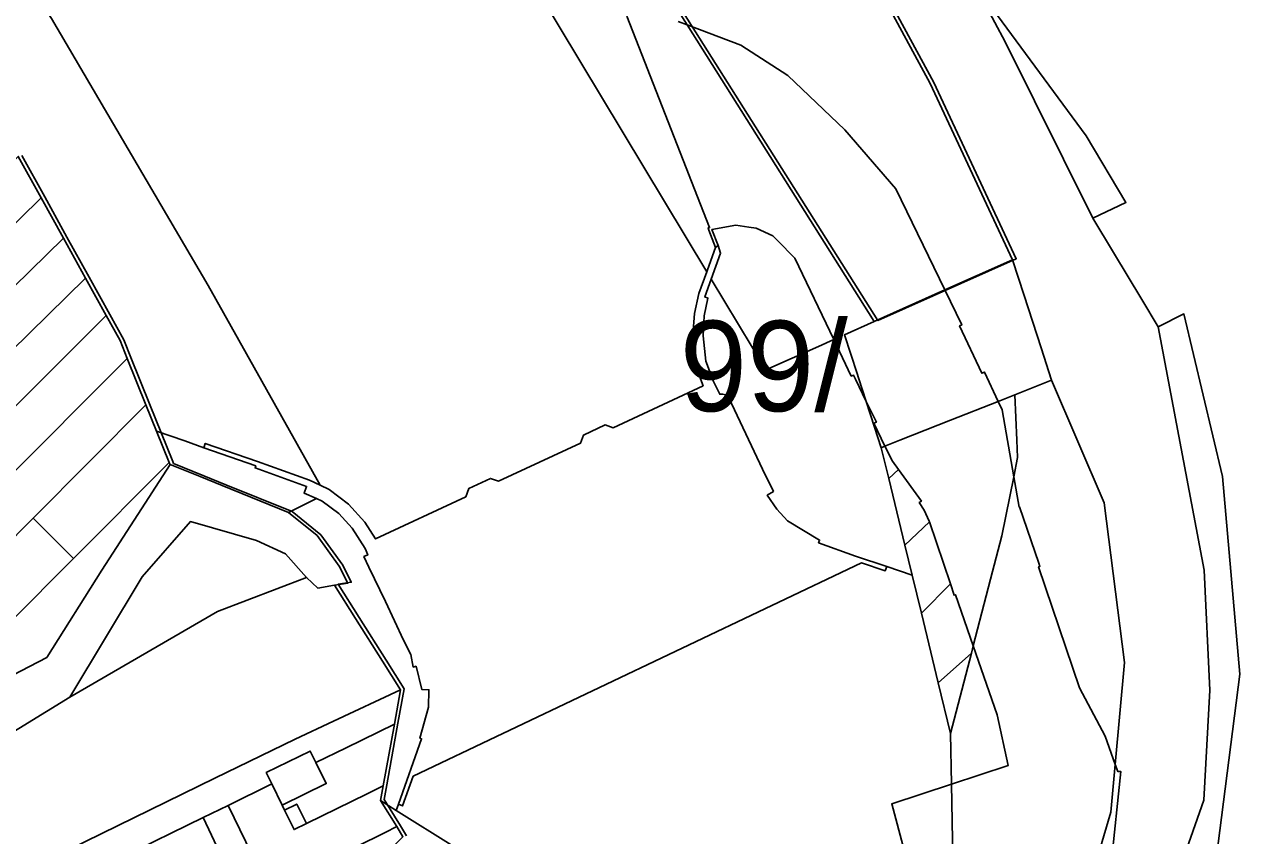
# Model space of a CAD drawing. Extents: x -535894 to -532827, y -1165802 to -1163635.
# Drawn here: x -533178.9 to -532977.3, y -1164904.6 to -1164770 of the extents above; entities that cross this region are included whole.
import ezdxf

# ---------------------------------------------------------------- set-up
doc = ezdxf.new("R2010")
doc.units = 0
for name, color, linetype in [('BPEJ_s', 7, 'Continuous'), ('orna_s', 7, 'Continuous'), ('ostatni_s', 7, 'Continuous'), ('trav_porost_s', 7, 'Continuous'), ('voda_s', 7, 'Continuous')]:
    doc.layers.add(name, color=color, linetype=linetype)

msp = doc.modelspace()

# ---------------------------------------------------------------- linework, layer by layer
at = {"layer": 'BPEJ_s'}
msp.add_lwpolyline([(-533064.041, -1164714.206), (-533051.48, -1164737.74), (-533049.69, -1164741.02), (-533048.53, -1164743.15), (-533047.398, -1164743.989), (-533028.041, -1164779.71), (-533014.38, -1164808.947), (-533037.332, -1164819.2), (-533075.566, -1164758.607), (-533078.437, -1164753.841), (-533082.42, -1164747.231), (-533086.574, -1164740.34), (-533089.802, -1164734.991), (-533093.522, -1164728.812), (-533097.748, -1164722.487), (-533099.729, -1164719.761), (-533174.02, -1164617.541), (-533177.323, -1164613.591), (-533144.122, -1164624.407), (-533120.195, -1164632.203), (-533112.188, -1164642.002), (-533098.703, -1164658.507), (-533086.643, -1164676.675), (-533076.582, -1164691.833)], close=True, dxfattribs=at)
for points in [[(-533174.02, -1164617.541), (-533099.729, -1164719.761), (-533097.748, -1164722.487), (-533093.522, -1164728.812), (-533089.802, -1164734.991), (-533086.574, -1164740.34), (-533082.42, -1164747.231), (-533078.437, -1164753.841), (-533075.566, -1164758.607), (-533037.332, -1164819.2), (-533014.38, -1164808.947), (-533028.041, -1164779.71), (-533047.398, -1164743.989), (-533021.38, -1164763.26), (-533002.77, -1164788.53), (-532996.17, -1164799.59), (-533001.68, -1164802.19), (-532998.25, -1164807.9), (-532993.57, -1164815.7), (-532990.84, -1164820.26), (-532986.56, -1164818.1), (-532980.17, -1164845.09), (-532977.31, -1164877.84), (-532981.22, -1164908.52)], [(-533179.324, -1164791.812), (-533175.539, -1164798.672), (-533171.846, -1164805.359), (-533168.169, -1164812.007), (-533164.734, -1164818.214), (-533162.439, -1164822.363), (-533161.248, -1164825.312), (-533158.139, -1164833.012), (-533154.284, -1164842.576), (-533154.149, -1164842.903), (-533149.163, -1164844.927), (-533145.487, -1164846.423), (-533134.501, -1164850.874), (-533129.737, -1164854.714), (-533126.072, -1164859.76), (-533124.678, -1164862.601), (-533126.87, -1164862.951), (-533123.37, -1164868.48), (-533118.912, -1164875.536), (-533115.91, -1164880.287), (-533116.935, -1164885.978), (-533118.768, -1164896.207)], [(-533115.501, -1164904.659), (-533116.533, -1164902.995), (-533119.211, -1164898.663), (-533118.768, -1164896.207), (-533116.935, -1164885.978), (-533115.91, -1164880.287), (-533118.912, -1164875.536), (-533123.37, -1164868.48), (-533126.87, -1164862.951), (-533124.678, -1164862.601), (-533126.072, -1164859.76), (-533129.737, -1164854.714), (-533134.501, -1164850.874), (-533145.487, -1164846.423), (-533149.163, -1164844.927), (-533154.149, -1164842.903), (-533154.284, -1164842.576), (-533158.139, -1164833.012), (-533161.248, -1164825.312), (-533162.439, -1164822.363), (-533164.734, -1164818.214), (-533168.169, -1164812.007), (-533171.846, -1164805.359), (-533175.539, -1164798.672), (-533179.324, -1164791.812)], [(-533118.768, -1164896.207), (-533119.211, -1164898.663), (-533116.533, -1164902.995), (-533115.501, -1164904.659)]]:
    msp.add_lwpolyline(points, dxfattribs=at)
at = {"layer": 'orna_s'}
for points in [[(-533176.14, -1164798.83), (-533282.57, -1164903.56), (-533293.4, -1164903.76), (-533179.93, -1164791.97)], [(-533172.45, -1164805.52), (-533272.33, -1164903.38), (-533282.57, -1164903.56), (-533176.14, -1164798.83)], [(-533168.77, -1164812.17), (-533261.52, -1164903.19), (-533272.33, -1164903.38), (-533172.45, -1164805.52)], [(-533165.34, -1164818.38), (-533229.86, -1164882.85), (-533251.03, -1164902.99), (-533261.52, -1164903.19), (-533168.77, -1164812.17)], [(-533163.04, -1164822.52), (-533161.85, -1164825.47), (-533182.9, -1164846.57), (-533235.8, -1164899.62), (-533249.36, -1164902.96), (-533251.03, -1164902.99), (-533229.86, -1164882.85), (-533165.34, -1164818.38)], [(-533158.74, -1164833.17), (-533177.43, -1164852), (-533220.52, -1164895.43), (-533225.42, -1164897.07), (-533235.8, -1164899.62), (-533182.9, -1164846.57), (-533161.85, -1164825.47)], [(-533156.99, -1164837.52), (-533154.89, -1164842.74), (-533170.75, -1164858.64), (-533177.43, -1164852), (-533158.74, -1164833.17)], [(-533154.75, -1164843.06), (-533166.05, -1164860.58), (-533175.17, -1164875.08), (-533189.49, -1164882.49), (-533200, -1164887.93), (-533192.13, -1164880.06), (-533170.75, -1164858.64), (-533154.89, -1164842.74)], [(-533170.75, -1164858.64), (-533192.13, -1164880.06), (-533200, -1164887.93), (-533203.49, -1164889.74), (-533220.52, -1164895.43), (-533177.43, -1164852)], [(-533149.26, -1164901.65), (-533145.13, -1164899.63), (-533138.32, -1164913.61), (-533119.06, -1164904.11), (-533117.14, -1164903.15), (-533116.11, -1164904.82), (-533137.69, -1164926.13), (-533141.88, -1164917.25)], [(-533149.26, -1164901.65), (-533141.88, -1164917.25), (-533157.58, -1164933.38), (-533260.52, -1165035.2), (-533294.68, -1165069.27), (-533316.06, -1165016.63), (-533241.31, -1164941.86), (-533238.5, -1164941.84), (-533229.28, -1164940.77)]]:
    msp.add_lwpolyline(points, close=True, dxfattribs=at)
at = {"layer": 'ostatni_s'}
for points in [[(-533216.56, -1164705.51), (-533174.44, -1164769.08), (-533148.43, -1164813.4), (-533129.85, -1164846.49), (-533131.61, -1164845.66), (-533140.25, -1164842.55), (-533148.9, -1164839.58), (-533149.14, -1164840.29), (-533152.31, -1164839.17), (-533156.99, -1164837.52), (-533158.74, -1164833.17), (-533161.85, -1164825.47), (-533163.04, -1164822.52), (-533165.34, -1164818.38), (-533168.77, -1164812.17), (-533172.45, -1164805.52), (-533176.14, -1164798.83), (-533179.93, -1164791.97)], [(-533078.96, -1164768.7), (-533065.26, -1164803.77), (-533065.5, -1164803.82), (-533065.36, -1164804.18), (-533064.29, -1164807.07), (-533065.61, -1164810.76), (-533065.72, -1164811.1), (-533107.67, -1164741.3)], [(-533076.17, -1164758.76), (-533068.98, -1164770.15), (-533070.48, -1164769.59)], [(-533070.48, -1164769.59), (-533068.98, -1164770.15), (-533037.94, -1164819.35), (-533042.84, -1164821.55), (-533040.76, -1164827.95), (-533040.53, -1164828.67), (-533039.27, -1164832.6), (-533041.05, -1164828.94), (-533041.39, -1164828.25), (-533041.74, -1164828.4), (-533044.65, -1164822.35), (-533051.13, -1164808.84), (-533054, -1164805.9), (-533054.77, -1164805.11), (-533057.54, -1164803.87), (-533058.72, -1164803.7), (-533060.9, -1164803.39), (-533064.85, -1164804.08), (-533063.85, -1164806.75), (-533064.29, -1164807.07), (-533065.36, -1164804.18), (-533065.5, -1164803.82), (-533065.26, -1164803.77), (-533078.96, -1164768.7)], [(-533236.41, -1164909.7), (-533192.2, -1164894.47), (-533171.4, -1164881.68), (-533146.9, -1164867.45), (-533132.1, -1164861.81), (-533130.26, -1164863.56), (-533127.47, -1164863.11), (-533123.98, -1164868.64), (-533119.52, -1164875.7), (-533116.52, -1164880.45), (-533127.62, -1164885.63), (-533134.02, -1164888.62), (-533147.32, -1164895.13), (-533230.7, -1164935.9)], [(-533230.7, -1164935.9), (-533147.32, -1164895.13), (-533134.02, -1164888.62), (-533127.62, -1164885.63), (-533116.52, -1164880.45), (-533117.54, -1164886.14), (-533125.56, -1164890.06), (-533130.56, -1164892.51), (-533131.5, -1164890.61), (-533138.79, -1164894.19), (-533137.86, -1164896.07), (-533145.13, -1164899.63), (-533149.26, -1164901.65), (-533229.28, -1164940.77)], [(-533116.11, -1164904.82), (-533117.14, -1164903.15), (-533119.82, -1164898.82), (-533117.22, -1164900.45), (-533098.11, -1164912.42)]]:
    msp.add_lwpolyline(points, dxfattribs=at)
for points in [[(-533016.19, -1164772.94), (-533021.38, -1164763.26), (-533002.77, -1164788.53), (-532996.17, -1164799.59), (-533001.68, -1164802.19)], [(-533068.98, -1164770.15), (-533060.06, -1164773.5), (-533052.26, -1164778.52), (-533042.8, -1164787.55), (-533034.33, -1164797.33), (-533026.23, -1164814.12), (-533037.94, -1164819.35)], [(-533058.72, -1164803.7), (-533057.54, -1164803.87), (-533054.77, -1164805.11), (-533054, -1164805.9), (-533051.13, -1164808.84), (-533044.65, -1164822.35), (-533047.16, -1164823.47), (-533055.93, -1164827.39), (-533064.98, -1164812.34), (-533063.41, -1164808.03), (-533063.85, -1164806.75), (-533064.85, -1164804.08), (-533060.9, -1164803.39)], [(-533063.85, -1164806.75), (-533063.41, -1164808.03), (-533064.98, -1164812.34), (-533066.05, -1164815.28), (-533065.52, -1164815.47), (-533066.12, -1164818.42), (-533066.32, -1164821.75), (-533065.88, -1164825.93), (-533064.62, -1164829.31), (-533063.56, -1164831.41), (-533063.04, -1164831.41), (-533062.61, -1164831.54), (-533062.18, -1164831.87), (-533061.94, -1164832.22), (-533061.6, -1164832.94), (-533059.24, -1164838), (-533056.49, -1164843.86), (-533054.66, -1164847.53), (-533055.68, -1164848.17), (-533054.08, -1164850.46), (-533052.32, -1164852.42), (-533047, -1164855.6), (-533047.16, -1164856.06), (-533041.04, -1164858.27), (-533035.87, -1164860.02), (-533036.12, -1164860.7), (-533040.05, -1164859.4), (-533114.4, -1164894.79), (-533116.17, -1164899.7), (-533116.87, -1164899.42), (-533113.01, -1164888.56), (-533113.29, -1164888.46), (-533111.9, -1164883.32), (-533111.8, -1164880.45), (-533113, -1164880.39), (-533113.94, -1164876.55), (-533114.4, -1164876.67), (-533114.81, -1164874.57), (-533116.02, -1164872.19), (-533119.01, -1164865.81), (-533121.79, -1164860.11), (-533122.6, -1164858.35), (-533121.94, -1164858.07), (-533122.39, -1164856.98), (-533124.52, -1164853.64), (-533126.75, -1164851.21), (-533129.49, -1164849.15), (-533130.46, -1164848.72), (-533132.52, -1164847.81), (-533132.11, -1164846.71), (-533140.65, -1164843.63), (-533140.54, -1164843.32), (-533149.14, -1164840.29), (-533148.9, -1164839.58), (-533140.25, -1164842.55), (-533131.61, -1164845.66), (-533129.85, -1164846.49), (-533128.35, -1164847.2), (-533125.12, -1164849.67), (-533122.43, -1164852.64), (-533120.66, -1164855.41), (-533105.69, -1164848.41), (-533105.21, -1164847.08), (-533101.59, -1164845.38), (-533100.24, -1164845.86), (-533086.66, -1164839.51), (-533086.18, -1164838.19), (-533082.55, -1164836.49), (-533081.23, -1164836.98), (-533066.32, -1164830), (-533067.67, -1164826.38), (-533068.04, -1164821.56), (-533067.75, -1164818), (-533067.05, -1164814.68), (-533065.72, -1164811.1), (-533065.61, -1164810.76), (-533064.29, -1164807.07)], [(-533014.98, -1164809.1), (-533013.07, -1164815.01), (-533010.27, -1164823.69), (-533008.53, -1164829.07), (-533014.61, -1164831.49), (-533017.38, -1164832.62), (-533019.64, -1164827.73), (-533020.06, -1164827.93), (-533023.77, -1164820.07), (-533023.43, -1164819.91), (-533026.23, -1164814.12)], [(-533064.98, -1164812.34), (-533055.93, -1164827.39), (-533047.16, -1164823.47), (-533044.65, -1164822.35), (-533041.74, -1164828.4), (-533041.39, -1164828.25), (-533041.05, -1164828.94), (-533039.27, -1164832.6), (-533037.87, -1164836.9), (-533036.78, -1164840.28), (-533035.54, -1164845.41), (-533032.87, -1164856.43), (-533031.66, -1164861.43), (-533035.87, -1164860.02), (-533041.04, -1164858.27), (-533047.16, -1164856.06), (-533047, -1164855.6), (-533052.32, -1164852.42), (-533054.08, -1164850.46), (-533055.68, -1164848.17), (-533054.66, -1164847.53), (-533056.49, -1164843.86), (-533059.24, -1164838), (-533061.6, -1164832.94), (-533061.94, -1164832.22), (-533062.18, -1164831.87), (-533062.61, -1164831.54), (-533063.04, -1164831.41), (-533063.56, -1164831.41), (-533064.62, -1164829.31), (-533065.88, -1164825.93), (-533066.32, -1164821.75), (-533066.12, -1164818.42), (-533065.52, -1164815.47), (-533066.05, -1164815.28)], [(-533026.23, -1164814.12), (-533023.43, -1164819.91), (-533023.77, -1164820.07), (-533020.06, -1164827.93), (-533019.64, -1164827.73), (-533017.38, -1164832.62), (-533025.28, -1164835.72), (-533033.7, -1164839.05), (-533036.16, -1164840.03), (-533037.98, -1164836.23), (-533037.58, -1164836.04), (-533039.27, -1164832.6), (-533040.53, -1164828.67), (-533040.76, -1164827.95), (-533042.84, -1164821.55), (-533037.94, -1164819.35)], [(-533008.53, -1164829.07), (-532999.79, -1164849.41), (-532996.43, -1164875.92), (-532997.96, -1164892.84), (-532999.62, -1164888.13), (-533003.87, -1164880.13), (-533010.66, -1164860.03), (-533010.45, -1164859.97), (-533010.63, -1164859.43), (-533013.81, -1164850.1), (-533013.9, -1164850.14), (-533014.78, -1164845.11), (-533014.15, -1164841.92), (-533014.28, -1164839.02), (-533014.61, -1164831.49)], [(-533037.58, -1164836.04), (-533037.98, -1164836.23), (-533036.16, -1164840.03), (-533036.78, -1164840.28), (-533037.87, -1164836.9), (-533039.27, -1164832.6)], [(-533017.38, -1164832.62), (-533016.73, -1164834.02), (-533014.78, -1164845.11), (-533016.75, -1164854.92), (-533018.63, -1164862.11), (-533021.51, -1164873.18), (-533024.46, -1164864.68), (-533024.68, -1164864.75), (-533025.3, -1164862.89), (-533028.77, -1164852.59), (-533028.81, -1164852.46), (-533029.63, -1164850.67), (-533030.47, -1164849.39), (-533030.1, -1164849.13), (-533033.92, -1164843.89), (-533034.93, -1164842.51), (-533036.16, -1164840.03), (-533033.7, -1164839.05), (-533025.28, -1164835.72)], [(-533014.61, -1164831.49), (-533014.28, -1164839.02), (-533014.15, -1164841.92), (-533014.78, -1164845.11), (-533016.73, -1164834.02), (-533017.38, -1164832.62)], [(-533152.31, -1164839.17), (-533149.14, -1164840.29), (-533140.54, -1164843.32), (-533140.65, -1164843.63), (-533132.11, -1164846.71), (-533132.52, -1164847.81), (-533130.46, -1164848.72), (-533135.11, -1164851.03), (-533146.09, -1164846.58), (-533149.77, -1164845.09), (-533154.75, -1164843.06), (-533154.89, -1164842.74), (-533156.99, -1164837.52)], [(-533036.16, -1164840.03), (-533034.93, -1164842.51), (-533033.92, -1164843.89), (-533035.54, -1164845.41), (-533036.78, -1164840.28)], [(-533035.54, -1164845.41), (-533033.92, -1164843.89), (-533030.1, -1164849.13), (-533030.47, -1164849.39), (-533029.63, -1164850.67), (-533028.81, -1164852.46), (-533028.77, -1164852.59), (-533032.87, -1164856.43)], [(-533013.9, -1164850.14), (-533013.81, -1164850.1), (-533010.63, -1164859.43), (-533010.45, -1164859.97), (-533010.66, -1164860.03), (-533003.87, -1164880.13), (-532999.62, -1164888.13), (-532997.96, -1164892.84), (-532998.67, -1164900.76), (-533005.49, -1164923.73), (-533009.67, -1164931.84), (-533010.36, -1164932.29), (-533012.47, -1164933.65), (-533014.17, -1164935.04), (-533016.06, -1164937.15), (-533024.33, -1164939.46), (-533024.62, -1164923.92), (-533025.13, -1164896.12), (-533015.73, -1164893.02), (-533017.56, -1164884.6), (-533021.51, -1164873.18), (-533018.63, -1164862.11), (-533016.75, -1164854.92), (-533014.78, -1164845.11)], [(-533129.49, -1164849.15), (-533126.75, -1164851.21), (-533124.52, -1164853.64), (-533122.39, -1164856.98), (-533121.94, -1164858.07), (-533122.6, -1164858.35), (-533121.79, -1164860.11), (-533119.01, -1164865.81), (-533116.02, -1164872.19), (-533114.81, -1164874.57), (-533114.4, -1164876.67), (-533113.94, -1164876.55), (-533113, -1164880.39), (-533111.8, -1164880.45), (-533111.9, -1164883.32), (-533113.29, -1164888.46), (-533113.01, -1164888.56), (-533116.87, -1164899.42), (-533117.22, -1164900.45), (-533119.82, -1164898.82), (-533119.37, -1164896.37), (-533117.54, -1164886.14), (-533116.52, -1164880.45), (-533119.52, -1164875.7), (-533123.98, -1164868.64), (-533127.47, -1164863.11), (-533125.28, -1164862.76), (-533126.68, -1164859.92), (-533130.34, -1164854.87), (-533135.11, -1164851.03), (-533130.46, -1164848.72)], [(-533032.87, -1164856.43), (-533028.77, -1164852.59), (-533025.3, -1164862.89), (-533030.12, -1164867.76), (-533031.66, -1164861.43)], [(-533024.46, -1164864.68), (-533021.51, -1164873.18), (-533021.81, -1164874.35), (-533027.33, -1164879.29), (-533030.12, -1164867.76), (-533025.3, -1164862.89), (-533024.68, -1164864.75)], [(-533027.33, -1164879.29), (-533021.81, -1164874.35), (-533025.29, -1164887.7)], [(-533021.81, -1164874.35), (-533021.51, -1164873.18), (-533017.56, -1164884.6), (-533015.73, -1164893.02), (-533025.13, -1164896.12), (-533025.29, -1164887.7)], [(-533125.56, -1164890.06), (-533117.54, -1164886.14), (-533119.37, -1164896.37), (-533122.04, -1164897.68), (-533132.1, -1164902.62), (-533133.74, -1164899.4), (-533135.74, -1164900.39), (-533136.13, -1164899.58), (-533128.85, -1164896.01), (-533130.56, -1164892.51)], [(-533131.5, -1164890.61), (-533130.56, -1164892.51), (-533128.85, -1164896.01), (-533136.13, -1164899.58), (-533137.86, -1164896.07), (-533138.79, -1164894.19)], [(-532997.96, -1164892.84), (-532997.55, -1164893.98), (-532997.02, -1164894.02), (-532998.63, -1164909.37), (-532994.46, -1164920.43), (-532998.95, -1164924.85), (-533001.85, -1164927.06), (-533003.92, -1164928.32), (-533006.56, -1164929.76), (-533009.67, -1164931.84), (-533005.49, -1164923.73), (-532998.67, -1164900.76)], [(-533122.04, -1164897.68), (-533119.37, -1164896.37), (-533119.82, -1164898.82), (-533117.14, -1164903.15), (-533119.06, -1164904.11), (-533138.32, -1164913.61), (-533145.13, -1164899.63), (-533137.86, -1164896.07), (-533136.13, -1164899.58), (-533135.74, -1164900.39), (-533134.16, -1164903.63), (-533132.1, -1164902.62)], [(-533035.02, -1164899.39), (-533025.13, -1164896.12), (-533024.62, -1164923.92), (-533024.33, -1164939.46)], [(-533135.74, -1164900.39), (-533133.74, -1164899.4), (-533132.1, -1164902.62), (-533134.16, -1164903.63)]]:
    msp.add_lwpolyline(points, close=True, dxfattribs=at)
at = {"layer": 'trav_porost_s'}
msp.add_lwpolyline([(-533050.15, -1164744.07), (-533048.53, -1164743.15), (-533028.64, -1164779.86), (-533014.98, -1164809.1), (-533026.23, -1164814.12), (-533034.33, -1164797.33), (-533042.8, -1164787.55), (-533052.26, -1164778.52), (-533060.06, -1164773.5), (-533068.98, -1164770.15), (-533076.17, -1164758.76), (-533063.86, -1164751.81)], close=True, dxfattribs=at)
at = {"layer": 'voda_s'}
for points in [[(-533187.88, -1164629.82), (-533107.67, -1164741.3), (-533065.72, -1164811.1), (-533067.05, -1164814.68), (-533067.75, -1164818), (-533068.04, -1164821.56), (-533067.67, -1164826.38), (-533066.32, -1164830), (-533081.23, -1164836.98), (-533082.55, -1164836.49), (-533086.18, -1164838.19), (-533086.66, -1164839.51), (-533100.24, -1164845.86), (-533101.59, -1164845.38), (-533105.21, -1164847.08), (-533105.69, -1164848.41), (-533120.66, -1164855.41), (-533122.43, -1164852.64), (-533125.12, -1164849.67), (-533128.35, -1164847.2), (-533129.85, -1164846.49), (-533148.43, -1164813.4), (-533174.44, -1164769.08), (-533216.56, -1164705.51)], [(-532998.63, -1164909.37), (-532997.02, -1164894.02), (-532997.55, -1164893.98), (-532997.96, -1164892.84), (-532996.43, -1164875.92), (-532999.79, -1164849.41), (-533008.53, -1164829.07), (-533010.27, -1164823.69), (-533013.07, -1164815.01), (-533014.98, -1164809.1), (-533028.64, -1164779.86), (-533048.53, -1164743.15), (-533021.38, -1164763.26), (-533016.19, -1164772.94), (-533001.68, -1164802.19), (-532998.25, -1164807.9), (-532993.57, -1164815.7), (-532990.84, -1164820.26), (-532983.21, -1164860.62), (-532982.29, -1164880.52), (-532983.25, -1164898.77), (-532988.28, -1164913.08)], [(-533189.49, -1164882.49), (-533175.17, -1164875.08), (-533166.05, -1164860.58), (-533154.75, -1164843.06), (-533149.77, -1164845.09), (-533146.09, -1164846.58), (-533135.11, -1164851.03), (-533130.34, -1164854.87), (-533126.68, -1164859.92), (-533125.28, -1164862.76), (-533127.47, -1164863.11), (-533130.26, -1164863.56), (-533132.1, -1164861.81), (-533135.59, -1164857.88), (-533140.4, -1164855.68), (-533151.38, -1164852.54), (-533159.38, -1164861.69), (-533171.4, -1164881.68), (-533192.2, -1164894.47)], [(-533098.11, -1164912.42), (-533117.22, -1164900.45), (-533116.87, -1164899.42), (-533116.17, -1164899.7), (-533114.4, -1164894.79), (-533040.05, -1164859.4), (-533036.12, -1164860.7), (-533035.87, -1164860.02), (-533031.66, -1164861.43), (-533030.12, -1164867.76), (-533027.33, -1164879.29), (-533025.29, -1164887.7), (-533025.13, -1164896.12), (-533035.02, -1164899.39), (-533024.33, -1164939.46)]]:
    msp.add_lwpolyline(points, dxfattribs=at)
for points in [[(-532990.84, -1164820.26), (-532986.56, -1164818.1), (-532980.17, -1164845.09), (-532977.31, -1164877.84), (-532981.22, -1164908.52), (-532991.79, -1164937.99), (-533005.91, -1164963.1), (-532996.56, -1164936.58), (-532993.75, -1164928.6), (-532988.28, -1164913.08), (-532983.25, -1164898.77), (-532982.29, -1164880.52), (-532983.21, -1164860.62)], [(-533151.38, -1164852.54), (-533140.4, -1164855.68), (-533135.59, -1164857.88), (-533132.1, -1164861.81), (-533146.9, -1164867.45), (-533171.4, -1164881.68), (-533159.38, -1164861.69)]]:
    msp.add_lwpolyline(points, close=True, dxfattribs=at)

# ---------------------------------------------------------------- texts
at = {"layer": 'BPEJ_s'}
msp.add_text('99/', height=15, dxfattribs=at).set_placement((-533070.195, -1164834.23))

doc.saveas('drawing.dxf')
